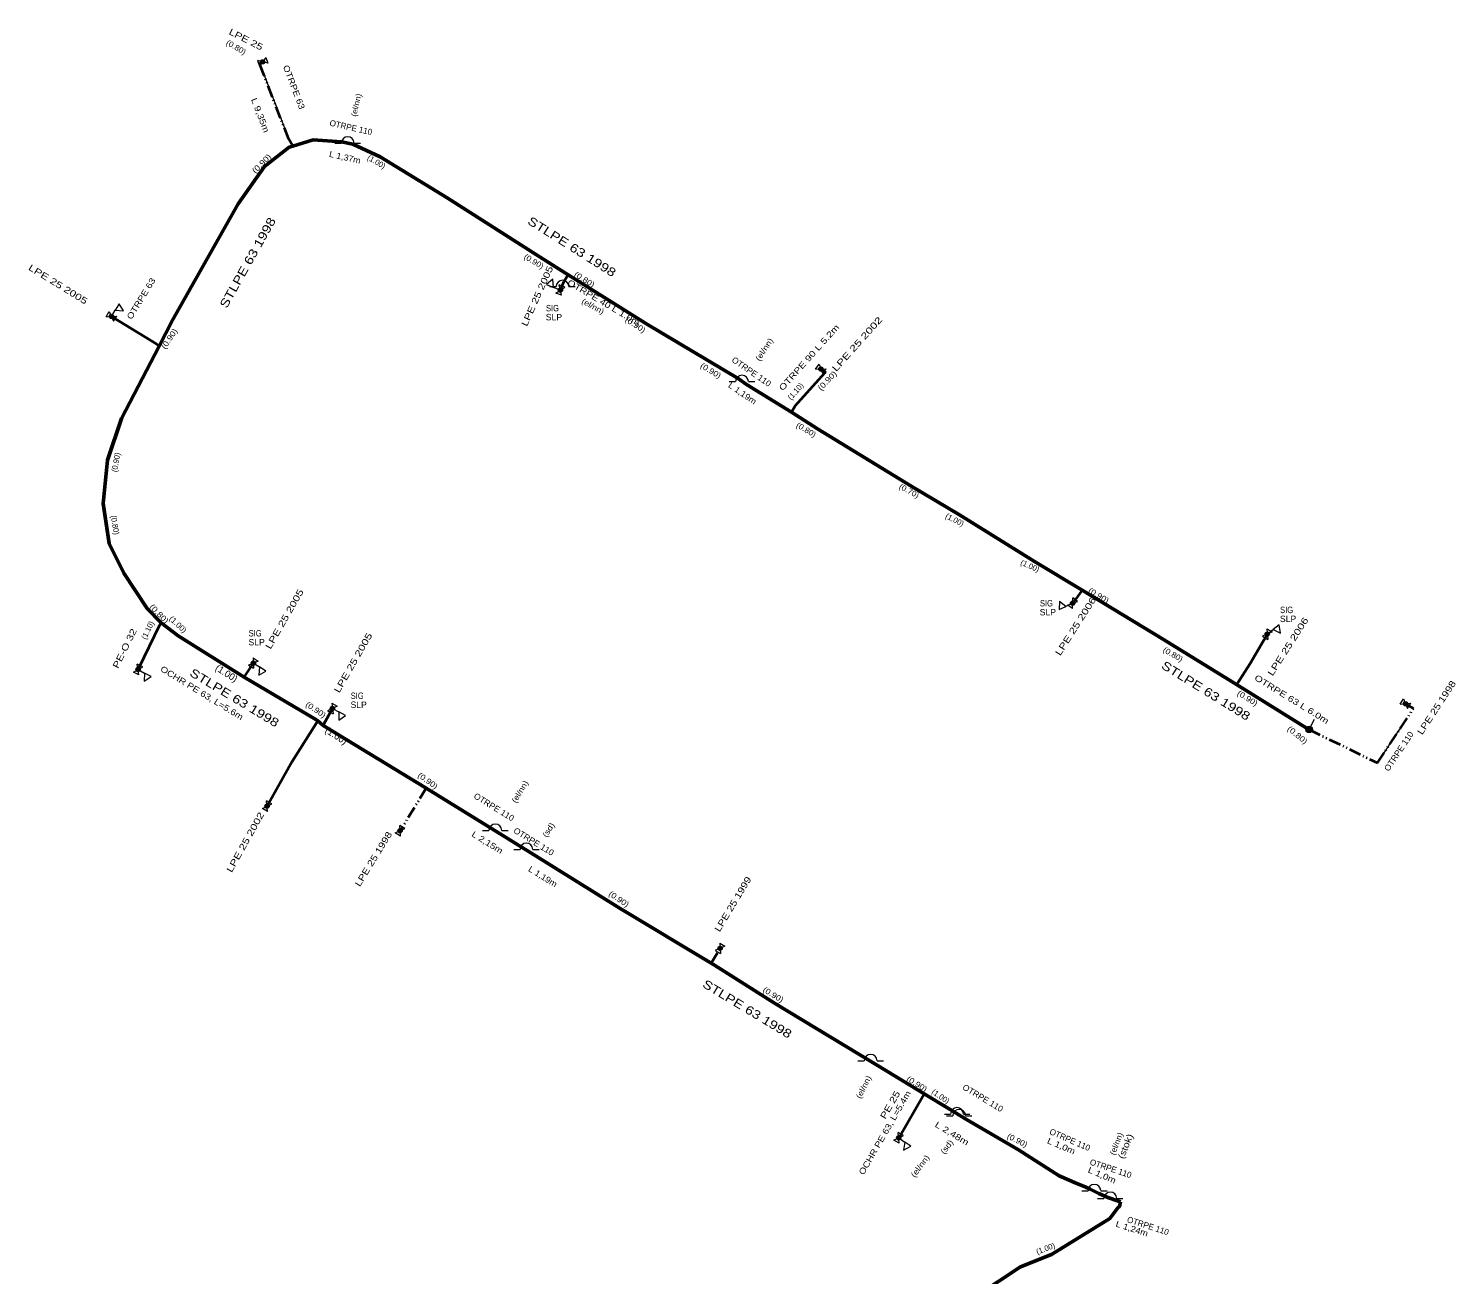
# Model space of a CAD drawing. Extents: x -648036 to -642998, y -1161549 to -1158141.
# Drawn here: x -647161.6 to -646995.6, y -1158290.6 to -1158145.7 of the extents above; entities that cross this region are included whole.
import ezdxf
from ezdxf.enums import TextEntityAlignment as Align

# ---------------------------------------------------------------- set-up
doc = ezdxf.new("R2010")
doc.units = 0
doc.header["$LTSCALE"] = 0.28
doc.linetypes.add('DASH_DOUBLE_DOT', pattern=[9.2, 5, -1.2, 0.3, -1.2, 0.3, -1.2])
for name, color, linetype, lineweight in [('12', 7, 'DASH_DOUBLE_DOT', 40), ('14', 7, 'Continuous', 13), ('15', 7, 'Continuous', 13), ('19', 7, 'Continuous', 13), ('8', 7, 'Continuous', 53)]:
    doc.layers.add(name, color=color, linetype=linetype, lineweight=lineweight)
for name, color, linetype in [('20', 7, 'Continuous'), ('22', 7, 'Continuous'), ('24', 7, 'Continuous'), ('27', 7, 'Continuous'), ('28', 7, 'Continuous'), ('35', 7, 'Continuous')]:
    doc.layers.add(name, color=color, linetype=linetype)

msp = doc.modelspace()

# ---------------------------------------------------------------- linework, layer by layer
at = {"layer": '12', "linetype": 'Continuous'}
msp.add_line((-647136.51, -1158221.16), (-647135.45, -1158219.5), dxfattribs=at)
at = {"layer": '12'}
for p, q in [((-647115.34, -1158234.07), (-647118.38, -1158239.01)), ((-647082.18, -1158254.4), (-647081.15, -1158252.69))]:
    msp.add_line(p, q, dxfattribs=at)
for points in [[(-647130.87, -1158159.38), (-647131.34, -1158158.54), (-647134.71, -1158149.81), (-647134.75, -1158149.7), (-647134.63, -1158149.65), (-647134.37, -1158149.56)], [(-647012.61, -1158227.24), (-647004.66, -1158231.11), (-647001.98, -1158227.09), (-647000.46, -1158224.79), (-647001.4, -1158224.23)]]:
    msp.add_lwpolyline(points, dxfattribs=at)
at = {"layer": '12', "linetype": 'Continuous'}
for points in [[(-647099.73, -1158176.12), (-647099.71, -1158176.07), (-647099.31, -1158175.17), (-647098.87, -1158174.37), (-647098.84, -1158174.32)], [(-647151.97, -1158179.17), (-647151.776, -1158179.29), (-647146.7, -1158182.42), (-647146.42, -1158182.65)], [(-647072.85, -1158190.32), (-647072.4, -1158189.58), (-647068.97, -1158185.73), (-647068.9, -1158185.65), (-647069.41, -1158185.31)], [(-647039.03, -1158211.03), (-647039.85, -1158212.16), (-647040.13, -1158212.55)], [(-647148.86, -1158220.25), (-647148.777, -1158220.079), (-647146.32, -1158215.04), (-647146.27, -1158214.94), (-647146.25, -1158214.92), (-647146.18, -1158214.84)], [(-647021.06, -1158222.01), (-647021, -1158221.92), (-647019.47, -1158219.55), (-647017.89, -1158216.84), (-647017.48, -1158216.13)], [(-647127.34, -1158226.75), (-647127.04, -1158226.26), (-647126.26, -1158224.78)], [(-647127.94, -1158226.21), (-647130.94, -1158230.97), (-647133.85, -1158236.14)], [(-647060.36, -1158274.73), (-647060.25, -1158274.54), (-647057.55, -1158269.87), (-647057.39, -1158269.621)]]:
    msp.add_lwpolyline(points, dxfattribs=at)
at = {"layer": '14'}
for p, q in [((-647134.71, -1158149.81), (-647131.34, -1158158.54)), ((-647125.2, -1158158.85), (-647123.86, -1158159.15)), ((-647099.71, -1158176.07), (-647099.31, -1158175.17)), ((-647151.776, -1158179.29), (-647146.7, -1158182.42)), ((-647079.05, -1158186.4), (-647078.07, -1158187.08)), ((-647068.97, -1158185.73), (-647072.4, -1158189.58)), ((-647146.32, -1158215.04), (-647148.777, -1158220.079)), ((-647004.66, -1158231.11), (-647001.98, -1158227.09)), ((-647108.25, -1158238.45), (-647106.42, -1158239.58)), ((-647103.18, -1158241.57), (-647104.19, -1158240.95)), ((-647060.25, -1158274.54), (-647057.55, -1158269.87)), ((-647054.58, -1158271.33), (-647052.46, -1158272.62)), ((-647039.63, -1158280.03), (-647038.68, -1158280.43)), ((-647038.07, -1158280.72), (-647037.07, -1158281.2)), ((-647034.81, -1158282.09), (-647036.02, -1158281.69))]:
    msp.add_line(p, q, dxfattribs=at)
msp.add_lwpolyline([(-647021, -1158221.92), (-647019.47, -1158219.55), (-647017.89, -1158216.84)], dxfattribs=at)
at = {"layer": '15'}
for p, q in [((-647134.962, -1158149.388), (-647134.73, -1158150.061)), ((-647133.777, -1158149.732), (-647134.962, -1158149.388)), ((-647134.01, -1158149.059), (-647134.73, -1158150.061)), ((-647134.01, -1158149.059), (-647133.777, -1158149.732)), ((-647125.955, -1158159.025), (-647125.22, -1158159.024)), ((-647123.734, -1158159.024), (-647123, -1158159.025)), ((-647100.955, -1158175.715), (-647100.22, -1158175.714)), ((-647099.73, -1158176.12), (-647100.526, -1158175.802)), ((-647100.248, -1158176.456), (-647099.213, -1158175.785)), ((-647099.587, -1158176.72), (-647100.248, -1158176.456)), ((-647099.213, -1158175.785), (-647099.873, -1158175.52)), ((-647099.587, -1158176.72), (-647099.873, -1158175.52)), ((-647098.734, -1158175.714), (-647098, -1158175.715)), ((-647152.586, -1158179.208), (-647152.212, -1158178.602)), ((-647152.586, -1158179.208), (-647151.354, -1158179.132)), ((-647152.212, -1158178.602), (-647151.729, -1158179.737)), ((-647151.97, -1158179.17), (-647151.52, -1158178.441)), ((-647151.729, -1158179.737), (-647151.354, -1158179.132)), ((-647070.027, -1158185.327), (-647069.632, -1158184.734)), ((-647069.632, -1158184.734), (-647069.189, -1158185.885)), ((-647070.027, -1158185.327), (-647068.793, -1158185.293)), ((-647069.189, -1158185.885), (-647068.793, -1158185.293)), ((-647080.075, -1158186.765), (-647079.34, -1158186.764)), ((-647077.854, -1158186.764), (-647077.12, -1158186.765)), ((-647040.13, -1158212.55), (-647040.906, -1158212.914)), ((-647040.713, -1158212.752), (-647039.547, -1158212.349)), ((-647040.135, -1158213.167), (-647040.713, -1158212.752)), ((-647040.135, -1158213.167), (-647040.125, -1158211.933)), ((-647039.547, -1158212.349), (-647040.125, -1158211.933)), ((-647016.92, -1158215.872), (-647018.04, -1158216.388)), ((-647018.04, -1158216.388), (-647017.424, -1158216.744)), ((-647017.536, -1158215.516), (-647017.424, -1158216.744)), ((-647017.536, -1158215.516), (-647016.92, -1158215.872)), ((-647017.48, -1158216.13), (-647016.802, -1158215.606)), ((-647148.32, -1158219.953), (-647148.96, -1158219.641)), ((-647148.76, -1158220.859), (-647148.96, -1158219.641)), ((-647134.879, -1158219.267), (-647136.021, -1158219.732)), ((-647136.021, -1158219.732), (-647135.421, -1158220.116)), ((-647135.479, -1158218.884), (-647135.421, -1158220.116)), ((-647135.479, -1158218.884), (-647134.879, -1158219.267)), ((-647135.45, -1158219.5), (-647134.728, -1158219.961)), ((-647149.4, -1158220.548), (-647148.32, -1158219.953)), ((-647148.76, -1158220.859), (-647149.4, -1158220.548)), ((-647148.86, -1158220.25), (-647148.11, -1158220.665)), ((-647125.71, -1158224.5), (-647126.809, -1158225.059)), ((-647126.34, -1158224.168), (-647126.18, -1158225.392)), ((-647126.34, -1158224.168), (-647125.71, -1158224.5)), ((-647126.26, -1158224.78), (-647125.502, -1158225.18)), ((-647002.015, -1158224.278), (-647001.651, -1158223.666)), ((-647002.015, -1158224.278), (-647000.785, -1158224.182)), ((-647001.651, -1158223.666), (-647001.15, -1158224.793)), ((-647001.15, -1158224.793), (-647000.785, -1158224.182)), ((-647126.809, -1158225.059), (-647126.18, -1158225.392)), ((-647012.61, -1158227.24), (-647012.003, -1158226.011)), ((-647134.407, -1158236.405), (-647133.293, -1158235.876)), ((-647133.787, -1158236.754), (-647134.407, -1158236.405)), ((-647133.293, -1158235.876), (-647133.913, -1158235.526)), ((-647133.787, -1158236.754), (-647133.913, -1158235.526)), ((-647118.947, -1158239.253), (-647117.813, -1158238.768)), ((-647118.341, -1158239.626), (-647118.947, -1158239.253)), ((-647117.813, -1158238.768), (-647118.419, -1158238.394)), ((-647118.341, -1158239.626), (-647118.419, -1158238.394)), ((-647108.775, -1158238.985), (-647108.04, -1158238.984)), ((-647106.554, -1158238.984), (-647105.82, -1158238.985)), ((-647105.155, -1158241.195), (-647104.42, -1158241.194)), ((-647102.934, -1158241.194), (-647102.2, -1158241.195)), ((-647080.585, -1158252.442), (-647081.714, -1158252.937)), ((-647081.714, -1158252.937), (-647081.105, -1158253.305)), ((-647081.195, -1158252.075), (-647081.105, -1158253.305)), ((-647081.195, -1158252.075), (-647080.585, -1158252.442)), ((-647065.105, -1158265.775), (-647064.37, -1158265.774)), ((-647062.884, -1158265.774), (-647062.15, -1158265.775)), ((-647055.055, -1158271.965), (-647054.32, -1158271.964)), ((-647054.805, -1158272.165), (-647054.07, -1158272.164)), ((-647052.834, -1158271.964), (-647052.1, -1158271.965)), ((-647052.584, -1158272.164), (-647051.85, -1158272.165)), ((-647060.921, -1158274.988), (-647059.8, -1158274.473)), ((-647059.8, -1158274.473), (-647060.416, -1158274.115)), ((-647060.304, -1158275.345), (-647060.416, -1158274.115)), ((-647060.304, -1158275.345), (-647060.921, -1158274.988)), ((-647060.36, -1158274.73), (-647059.657, -1158275.22)), ((-647039.075, -1158280.895), (-647038.34, -1158280.894)), ((-647036.854, -1158280.894), (-647036.12, -1158280.895)), ((-647037.225, -1158281.795), (-647036.49, -1158281.794)), ((-647035.004, -1158281.794), (-647034.27, -1158281.795))]:
    msp.add_line(p, q, dxfattribs=at)
for points in [[(-647100.526, -1158175.802), (-647100.611, -1158174.844), (-647101.333, -1158175.479)], [(-647151.52, -1158178.441), (-647150.562, -1158178.52), (-647151.063, -1158177.7)], [(-647040.906, -1158212.914), (-647041.664, -1158212.324), (-647041.693, -1158213.284)], [(-647016.802, -1158215.606), (-647015.934, -1158216.019), (-647016.113, -1158215.074)], [(-647148.11, -1158220.665), (-647148.144, -1158221.625), (-647147.348, -1158221.085)], [(-647134.728, -1158219.961), (-647134.822, -1158220.918), (-647133.994, -1158220.429)], [(-647125.502, -1158225.18), (-647125.517, -1158226.141), (-647124.732, -1158225.585)], [(-647059.657, -1158275.22), (-647059.79, -1158276.172), (-647058.943, -1158275.718)]]:
    msp.add_lwpolyline(points, close=True, dxfattribs=at)
for radius in [0.381, 0.2858, 0.2143, 0.1072]:
    msp.add_circle((-647012.61, -1158227.24), radius, dxfattribs=at)
for centre in [(-647124.4774, -1158159.0246), (-647099.4774, -1158175.7146), (-647078.5974, -1158186.7646), (-647107.2974, -1158238.9846), (-647103.6774, -1158241.1946), (-647063.6274, -1158265.7746), (-647053.5774, -1158271.9646), (-647053.3274, -1158272.1646), (-647037.5974, -1158280.8946), (-647035.7474, -1158281.7946)]:
    msp.add_arc(centre, 0.7431, 1.2748, 179.83951, dxfattribs=at)
at = {"layer": '19'}
for centre, radius in [((-647134.37, -1158149.56), 0.25), ((-647134.37, -1158149.56), 0.17), ((-647134.37, -1158149.56), 0.09), ((-647099.73, -1158176.12), 0.25), ((-647099.73, -1158176.12), 0.17), ((-647099.73, -1158176.12), 0.09), ((-647151.97, -1158179.17), 0.25), ((-647151.97, -1158179.17), 0.17), ((-647151.97, -1158179.17), 0.09), ((-647069.41, -1158185.31), 0.25), ((-647069.41, -1158185.31), 0.17), ((-647069.41, -1158185.31), 0.09), ((-647040.13, -1158212.55), 0.25), ((-647040.13, -1158212.55), 0.17), ((-647040.13, -1158212.55), 0.09), ((-647017.48, -1158216.13), 0.25), ((-647017.48, -1158216.13), 0.17), ((-647017.48, -1158216.13), 0.09), ((-647135.45, -1158219.5), 0.25), ((-647135.45, -1158219.5), 0.17), ((-647135.45, -1158219.5), 0.09), ((-647148.86, -1158220.25), 0.25), ((-647148.86, -1158220.25), 0.17), ((-647148.86, -1158220.25), 0.09), ((-647126.26, -1158224.78), 0.25), ((-647126.26, -1158224.78), 0.17), ((-647126.26, -1158224.78), 0.09), ((-647001.4, -1158224.23), 0.25), ((-647001.4, -1158224.23), 0.17), ((-647001.4, -1158224.23), 0.09), ((-647133.85, -1158236.14), 0.25), ((-647133.85, -1158236.14), 0.17), ((-647133.85, -1158236.14), 0.09), ((-647118.38, -1158239.01), 0.25), ((-647118.38, -1158239.01), 0.17), ((-647118.38, -1158239.01), 0.09), ((-647081.15, -1158252.69), 0.25), ((-647081.15, -1158252.69), 0.17), ((-647081.15, -1158252.69), 0.09), ((-647060.36, -1158274.73), 0.25), ((-647060.36, -1158274.73), 0.17), ((-647060.36, -1158274.73), 0.09)]:
    msp.add_circle(centre, radius, dxfattribs=at)
at = {"layer": '8'}
for points in [[(-647146.42, -1158182.65), (-647144.85, -1158179.63), (-647137.21, -1158166.09), (-647134.15, -1158161.72), (-647131.27, -1158159.5), (-647130.87, -1158159.38)], [(-647130.87, -1158159.38), (-647128.49, -1158158.64), (-647125.2, -1158158.85), (-647123.86, -1158159.15), (-647120.68, -1158160.6), (-647112.92, -1158165.37), (-647102.09, -1158172.29), (-647098.84, -1158174.32)], [(-647098.84, -1158174.32), (-647089.61, -1158180.1), (-647079.05, -1158186.4), (-647078.07, -1158187.08), (-647072.85, -1158190.32)], [(-647146.18, -1158214.84), (-647147.81, -1158213.14), (-647150.53, -1158209.03), (-647152.22, -1158205.59), (-647152.93, -1158200.94), (-647152.43, -1158195.89), (-647150.78, -1158191.05), (-647146.42, -1158182.65)], [(-647072.85, -1158190.32), (-647069.81, -1158192.24), (-647058.82, -1158198.98), (-647053.29, -1158202.26), (-647044.58, -1158207.68), (-647039.03, -1158211.03)], [(-647039.03, -1158211.03), (-647029.54, -1158216.76), (-647021.06, -1158222.01)], [(-647136.51, -1158221.16), (-647144.21, -1158216.35), (-647146.18, -1158214.84)], [(-647127.94, -1158226.21), (-647128.18, -1158226.06), (-647136.51, -1158221.16)], [(-647021.06, -1158222.01), (-647012.63, -1158227.23), (-647012.61, -1158227.24)], [(-647082.18, -1158254.4), (-647092.77, -1158248.05), (-647103.18, -1158241.57), (-647104.19, -1158240.95), (-647106.42, -1158239.58), (-647108.25, -1158238.45), (-647115.34, -1158234.07), (-647127.34, -1158226.75), (-647127.94, -1158226.21)], [(-647057.39, -1158269.621), (-647061.65, -1158267.03), (-647074.8, -1158259.07), (-647081.8, -1158254.63), (-647082.18, -1158254.4)], [(-647034.56, -1158282.17), (-647034.81, -1158282.09), (-647036.02, -1158281.69), (-647037.07, -1158281.2), (-647038.07, -1158280.72), (-647038.68, -1158280.43), (-647039.63, -1158280.03), (-647041.68, -1158279.14), (-647046.42, -1158276.12), (-647052.46, -1158272.62), (-647054.58, -1158271.33), (-647057.39, -1158269.621)], [(-647083.86, -1158314.081), (-647076.45, -1158309.35), (-647062.52, -1158300.47), (-647061.65, -1158299.96), (-647046.21, -1158289.73), (-647042.6, -1158288.3), (-647035.8, -1158284.11), (-647034.86, -1158282.89), (-647034.69, -1158282.73), (-647034.56, -1158282.17)]]:
    msp.add_lwpolyline(points, dxfattribs=at)

# ---------------------------------------------------------------- texts
at = {"layer": '15', "width": 0.85}
for p in [(-647100.6485, -1158178.588), (-647043.1795, -1158212.916), (-647015.2305, -1158213.691), (-647135.2385, -1158216.407), (-647123.3685, -1158223.682)]:
    msp.add_text('SIG', height=0.75, dxfattribs=at).set_placement(p, align=Align.CENTER)
at = {"layer": '15'}
for p in [(-647100.479, -1158179.632), (-647043.01, -1158213.96), (-647015.061, -1158214.735), (-647135.069, -1158217.451), (-647123.199, -1158224.726)]:
    msp.add_text('SLP', height=0.75, dxfattribs=at).set_placement(p, align=Align.CENTER)
at = {"layer": '20', "width": 1.25}
for rotation, p in [(60.734, (-647135.6729, -1158173.1694)), (327.732, (-647098.6564, -1158171.4889)), (328.305, (-647024.8822, -1158223.1469)), (328.878, (-647137.9084, -1158223.9647)), (328.878, (-647078.2484, -1158260.1647))]:
    msp.add_text('STLPE 63 1998', height=1, rotation=rotation, dxfattribs=at).set_placement(p, align=Align.CENTER)
at = {"layer": '22'}
for s, rotation, width, p in [('LPE 25', 332.888, 1.3, (-647136.4799, -1158147.2811)), ('LPE 25 2005', 328.305, 1.35, (-647158.373, -1158175.7565)), ('LPE 25 2005', 65.89, 1.3, (-647102.0786, -1158176.9647)), ('LPE 25 2002', 48.128, 1.4, (-647064.9244, -1158182.6463)), ('LPE 25 2005', 60.161, 1.35, (-647131.5062, -1158214.5666)), ('PE-O 32', 63.752, 1.3, (-647150.0862, -1158217.9638)), ('LPE 25 2005', 60.161, 1.35, (-647123.5162, -1158219.6566)), ('LPE 25 1998', 56.723, 1.25, (-646997.4714, -1158224.8903)), ('LPE 25 2002', 60.734, 1.35, (-647136.0632, -1158240.5243)), ('LPE 25 1998', 58.442, 1.25, (-647121.1631, -1158242.4953)), ('LPE 25 1999', 59.015, 1.25, (-647079.332, -1158247.7401)), ('PE 25', 60.001, 1.3, (-647061.0374, -1158271.088))]:
    msp.add_text(s, height=0.75, rotation=rotation, dxfattribs=dict(at, width=width)).set_placement(p, align=Align.CENTER)
at = {"layer": '22', "width": 1.35}
for p in [(-647041.58, -1158218.72), (-647016.87, -1158221.08)]:
    msp.add_text('LPE 25 2006', height=0.75, rotation=57.296, dxfattribs=at).set_placement(p)
at = {"layer": '24'}
for s, rotation, width, p in [('OTRPE 63', 291.063, 1.2, (-647131.0506, -1158152.6282)), ('L 9,35m', 291.063, 1.25, (-647134.9788, -1158155.8997)), ('L 1,37m', 347.212, 1.1, (-647124.8705, -1158161.0085)), ('OTRPE 63', 58.442, 1.2, (-647148.2101, -1158177.2857)), ('OTRPE 40 L 1.0m', 329.451, 1.25, (-647094.8714, -1158177.8663)), ('OTRPE 90 L 5.2m', 48.128, 1.3, (-647070.5377, -1158184.1941)), ('OTRPE 110', 325.44, 1.05, (-647077.695, -1158185.8994)), ('L 1,19m', 325.44, 1.1, (-647078.7435, -1158188.4079)), ('OCHR PE 63, L=5.6m', 328.515, 1.2, (-647141.6208, -1158223.2759)), ('OTRPE 110', 56.15, 1.05, (-647001.8826, -1158229.9655)), ('OTRPE 110', 328.305, 1.05, (-647107.6369, -1158236.5475)), ('L 2,15m', 328.305, 1.2, (-647108.4134, -1158240.6678)), ('OTRPE 110', 328.305, 1.05, (-647103.0069, -1158240.5675)), ('L 1,19m', 328.305, 1.1, (-647101.9549, -1158244.635)), ('OCHR PE 63, L=5.4m', 59.966, 1.2, (-647061.6802, -1158274.3242)), ('OTRPE 110', 328.878, 1.05, (-647050.7514, -1158270.4051)), ('L 2,48m', 328.878, 1.3, (-647054.3519, -1158274.5215)), ('L 1,0m', 336.899, 1.2, (-647041.5863, -1158276.0069)), ('L 1,0m', 336.899, 1.2, (-647036.8463, -1158279.3969)), ('L 1,24m', 342.056, 1.15, (-647033.3368, -1158285.6325))]:
    msp.add_text(s, height=0.7, rotation=rotation, dxfattribs=dict(at, width=width)).set_placement(p, align=Align.CENTER)
for rotation, p in [(347.212, (-647124.1755, -1158157.5398)), (336.326, (-647040.587, -1158275.2772)), (341.483, (-647035.8052, -1158278.6352)), (342.056, (-647031.4688, -1158285.3056))]:
    msp.add_text('OTRPE 110', height=0.7, rotation=rotation, dxfattribs=at).set_placement(p, align=Align.CENTER)
at = {"layer": '24', "width": 1.3}
msp.add_text('OTRPE 63 L 6.0m', height=0.7, rotation=328.305, dxfattribs=at).set_placement((-647019.05, -1158221.4))
at = {"layer": '27'}
for s, rotation, width, p in [('(0.80)', 329.451, 1.1, (-647137.6202, -1158148.1353)), ('(el/nn)', 76.776, 1.1, (-647123.1752, -1158154.6608)), ('(0.90)', 45.264, 1.2, (-647134.2668, -1158161.6252)), ('(0.90)', 329.451, 1.1, (-647102.9752, -1158173.0445)), ('(0.80)', 328.305, 1.15, (-647097.1033, -1158175.1514)), ('(el/nn)', 331.17, 1.15, (-647096.0957, -1158178.2839)), ('(0.90)', 327.159, 1.15, (-647091.1813, -1158180.4172)), ('(0.90)', 56.15, 1.15, (-647144.9669, -1158181.956)), ('(el/nn)', 56.723, 1.2, (-647075.741, -1158183.1968)), ('(0.90)', 328.878, 1.15, (-647082.4015, -1158185.7573)), ('(0.90)', 46.41, 1.2, (-647068.4482, -1158186.8711)), ('(0.80)', 328.878, 1.1, (-647071.2965, -1158192.6381)), ('(0.70)', 331.743, 1.1, (-647059.3064, -1158199.753)), ('(0.90)', 328.878, 1.15, (-647037.2675, -1158211.9143)), ('(0.80)', 313.796, 1.2, (-647146.6498, -1158213.9901)), ('(1.10)', 64.01, 0.95, (-647147.4609, -1158215.8219)), ('(1.00)', 317.419, 1.05, (-647144.4429, -1158215.2397)), ('(0.80)', 330.024, 1.1, (-647028.6134, -1158218.7733)), ('(0.90)', 328.305, 1.15, (-647019.9513, -1158223.8596)), ('(0.90)', 326.013, 1.15, (-647128.3652, -1158225.1937)), ('(0.80)', 320.283, 1.2, (-647014.1767, -1158228.1139)), ('(0.90)', 324.867, 1.15, (-647115.3385, -1158233.4513)), ('(el/nn)', 58.442, 1.15, (-647104.1555, -1158234.6341)), ('(sd)', 57.296, 1.2, (-647100.8365, -1158239.0891)), ('(0.90)', 326.586, 1.15, (-647093.098, -1158247.2202)), ('(0.90)', 328.305, 1.15, (-647075.1383, -1158258.3606)), ('(el/nn)', 63.025, 1.15, (-647064.1507, -1158268.9739)), ('(0.90)', 328.404, 1.15, (-647058.4203, -1158268.7372)), ('(0.90)', 332.888, 1.1, (-647046.7141, -1158275.3086)), ('(el/nn)', 68.182, 1.1, (-647034.7436, -1158275.5383)), ('(sd)', 53.285, 1.2, (-647054.5058, -1158275.9798)), ('(el/nn)', 53.858, 1.2, (-647057.6149, -1158278.2167))]:
    msp.add_text(s, height=0.65, rotation=rotation, dxfattribs=dict(at, width=width)).set_placement(p, align=Align.CENTER)
for s, rotation, p in [('(1.00)', 330.024, (-647121.2924, -1158161.47)), ('(1.10)', 48.701, (-647072.1205, -1158188.106)), ('(0.90)', 79.641, (-647151.1281, -1158196.2044)), ('(0.80)', 279.03, (-647151.8608, -1158203.491)), ('(1.00)', 332.888, (-647053.9996, -1158203.1204)), ('(1.00)', 335.753, (-647045.2285, -1158208.4922)), ('(1.00)', 324.867, (-647055.6785, -1158270.1757)), ('(1.00)', 20.626, (-647043.1615, -1158287.9159))]:
    msp.add_text(s, height=0.65, rotation=rotation, dxfattribs=at).set_placement(p, align=Align.CENTER)
at = {"layer": '28', "width": 1.2}
msp.add_text('(stok)', height=0.75, rotation=67.609, dxfattribs=at).set_placement((-647033.6275, -1158275.8573), align=Align.CENTER)
at = {"layer": '35'}
for p in [(-647138.7894, -1158221.0167), (-647126.0294, -1158228.2767)]:
    msp.add_text('(1.00)', height=0.8, rotation=327.159, dxfattribs=at).set_placement(p, align=Align.CENTER)

doc.saveas('drawing.dxf')
